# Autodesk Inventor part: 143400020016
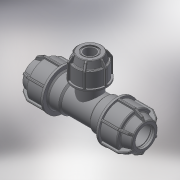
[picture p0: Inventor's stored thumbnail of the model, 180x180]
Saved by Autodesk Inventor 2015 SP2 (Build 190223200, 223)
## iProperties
Created: 2017-08
Part Number: 143400020016
Material: Generic
Description: PLASSON L.14 TEE REDUCER (SILVER) 20-16-20
Document SubType Name: Modeling
Designer: KIM
Density: 1 g/cm^3
Appearance: Default
Author: KIM
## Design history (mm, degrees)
derived "143400.ipt"
feature "Solid1::143400.ipt"
feature "Solid2::143400.ipt"
tag "TaggingFeature1"
body "Solid1"
body "Solid2"
other parameters: "d2" = 44, "d4" = 15 deg, "d5" = 29.04, "d6" = 9.5832, "d10" = 42, "d16" = 20.4, "d17" = 2.2, "d22" = 32, "d24" = 2.2, "d25" = 37.8, "d26" = 31.5, "d27" = 2.2, "d28" = 135 deg, "d29" = 1.32, "d31" = 1, "d46" = 150 deg, "d49" = 2.1, "d50" = 0, "d58" = 0.6, "d61" = 360 deg, "d63" = 18, "d64" = 56.5, "d80" = 28.8, "d81" = 1.6, "d84" = 2.2, "d94" = 48, "d108" = 0.6, "d111" = 0, "d113" = 11.2, "d114" = 34, "d115" = 17, "d116" = 1.7, "d118" = 24, "d119" = 7.2, "d120" = 30.6, "d121" = 26.52, "d122" = 13 deg, "d123" = 16, "d124" = 0.48, "d125" = 1.44, "d126" = 17.6, "d127" = 13.6, "d128" = 22.4, "d129" = 15 deg, "d130" = 2.1, "d131" = 0, "d132" = 1.6, "d133" = 0.32, "d135" = 360 deg, "d_1" = 16, "E_" = 42, "L_" = 113, "l_" = 44, "l_2" = 17, "A_" = 48, "E_1" = 34
